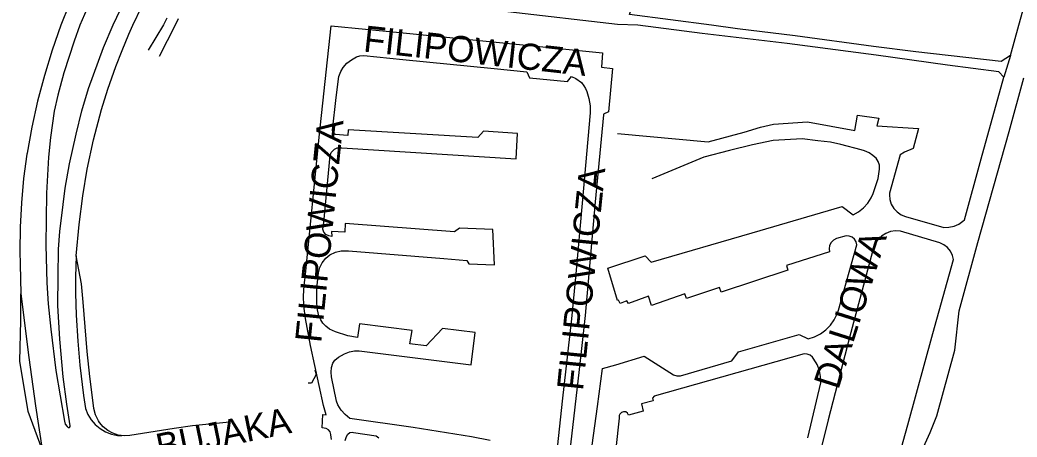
# Model space of a CAD drawing. Extents: x -304109 to -273954, y 21500 to 39796.
# Drawn here: x -293427.4 to -293046.9, y 26092.8 to 26252 of the extents above; entities that cross this region are included whole.
import ezdxf

# ---------------------------------------------------------------- set-up
doc = ezdxf.new("R2010")
doc.units = 0
doc.layers.add('krawedzie_ulic', color=7, linetype='Continuous')
doc.layers.add('nazwy_ulic', color=7, linetype='Continuous')

msp = doc.modelspace()

# ---------------------------------------------------------------- linework, layer by layer
at = {"layer": 'krawedzie_ulic'}
for points in [[(-293049.422, 26238.461), (-293046.255, 26250), (-293020.945, 26340.252), (-293018.58, 26349.347), (-293017.527, 26354.28), (-293015.976, 26362.706), (-293013.596, 26376.987), (-293012.654, 26382.031), (-293010.327, 26390.789), (-293006.508, 26405.341), (-293001.971, 26421.717), (-293001.307, 26425.819)], [(-293049.422, 26238.461), (-293052.975, 26236.155), (-293085.447, 26239.764), (-293101.608, 26241.861), (-293131.537, 26245.9), (-293153.518, 26248.648), (-293163.414, 26250), (-293194.727, 26254.097), (-293187.743, 26275.442), (-293180.973, 26295.729), (-293171.969, 26313.451), (-293167.518, 26323.093), (-293146.198, 26368.223), (-293143.014, 26376.286), (-293140.282, 26384.213)], [(-293399.999, 26260.275), (-293404.455, 26249.968), (-293406.699, 26243.829), (-293410.626, 26231.78), (-293412.907, 26223.216), (-293414.318, 26217.187), (-293415.766, 26207.122), (-293416.414, 26199.62), (-293417.252, 26185.828), (-293417.519, 26166.006), (-293417.064, 26151.722), (-293416.644, 26143.669), (-293415.577, 26134.038), (-293413.711, 26118.178), (-293410.365, 26098.884), (-293410.051, 26097.769), (-293409.379, 26096.825), (-293408.973, 26096.482), (-293408.513, 26096.517), (-293408.237, 26096.887), (-293408.229, 26097.073), (-293409.447, 26105.35), (-293410.82, 26115.769), (-293412.192, 26130.165), (-293412.877, 26143.083), (-293412.802, 26154.056), (-293412.611, 26164.474), (-293412.117, 26171.248), (-293410.82, 26181.59), (-293410.058, 26187.752), (-293408.422, 26197.084), (-293405.866, 26208.456), (-293403.736, 26217.244), (-293401.219, 26225.869), (-293395.466, 26241.42), (-293391.766, 26250.083), (-293386.347, 26261.657)], [(-293408.632, 26257.912), (-293411.755, 26250), (-293415.098, 26240.45), (-293418.061, 26230.775), (-293420.639, 26220.99), (-293422.828, 26211.111), (-293424.626, 26201.153), (-293424.697, 26200.705), (-293425.962, 26191.479), (-293426.831, 26182.208), (-293427.3, 26172.907), (-293427.369, 26163.596), (-293427.249, 26158.799), (-293427.057, 26147.446)], [(-293405.86, 26161.936), (-293404.755, 26173.897), (-293403.421, 26184.91), (-293401.707, 26195.049), (-293399.267, 26206.177), (-293396.257, 26217.76), (-293393.854, 26225.546), (-293390.77, 26234.189), (-293388.405, 26240.257), (-293385.817, 26246.572), (-293384.253, 26250.006), (-293380.862, 26257.113)], [(-293051.878, 26230.178), (-293053.847, 26232.143), (-293073.434, 26234.684), (-293100.613, 26238.48), (-293134.655, 26242.948), (-293167.001, 26246.786), (-293191.644, 26250), (-293199.376, 26250.243), (-293241.201, 26255.126)], [(-293371.322, 26252.653), (-293372.606, 26250.117), (-293378.451, 26240.425)], [(-293366.929, 26252.379), (-293368.108, 26250.021), (-293374.265, 26238.023)], [(-293308.538, 26091.929), (-293308.687, 26093.672), (-293308.697, 26093.877), (-293308.985, 26094.858), (-293309.624, 26095.657), (-293310.518, 26096.153), (-293312.082, 26096.42), (-293311.777, 26101.419), (-293310.552, 26101.287), (-293311.506, 26104.913), (-293316.456, 26127.809), (-293318.342, 26138.122), (-293319.023, 26142.893), (-293319.213, 26146.755), (-293318.91, 26150.693), (-293318.457, 26154.869), (-293313.239, 26207.239), (-293308.55, 26249.673), (-293282.434, 26247.216), (-293205.084, 26239.431), (-293205.5, 26233.979), (-293201.224, 26233.487), (-293202.813, 26216.919), (-293204.667, 26216.049), (-293204.71, 26215.836), (-293207.909, 26182.534), (-293211.718, 26139.272), (-293213.968, 26118.62), (-293217.248, 26089.909)], [(-293247.945, 26091.493), (-293255.078, 26092.943), (-293277.308, 26096.454), (-293301.526, 26099.922), (-293303.312, 26101.396), (-293304.819, 26103.154), (-293306.001, 26105.145), (-293306.561, 26106.487), (-293308.522, 26115.768), (-293308.667, 26117.649), (-293308.516, 26119.428), (-293308.024, 26121.019), (-293307.154, 26122.155), (-293305.829, 26123.29), (-293303.521, 26124.54), (-293301.553, 26125.297), (-293299.737, 26125.676), (-293297.958, 26125.676), (-293255.132, 26120.406), (-293253.626, 26132.77), (-293266.139, 26134.276), (-293272.369, 26127.627), (-293278.548, 26128.354), (-293277.702, 26133.497), (-293297.794, 26136.095), (-293298.521, 26130.796), (-293302.278, 26131.491), (-293306.932, 26133.006), (-293309.203, 26133.99), (-293310.679, 26135.088), (-293311.776, 26136.262), (-293312.608, 26137.549), (-293313.327, 26139.14), (-293313.78, 26141.441), (-293314.082, 26143.902), (-293314.043, 26149.532), (-293313.475, 26155.552), (-293312.87, 26157.585), (-293312.038, 26159.289), (-293310.676, 26161.107), (-293309.162, 26162.394), (-293307.005, 26163.417), (-293304.773, 26163.833), (-293303.07, 26163.871), (-293301.972, 26163.833), (-293265.602, 26160.987), (-293256.795, 26160.208), (-293256.017, 26158.961), (-293246.308, 26158.597), (-293246.879, 26172.052), (-293259.651, 26172.52), (-293261.52, 26171.169), (-293303.294, 26174.334), (-293303.406, 26170.969), (-293308.434, 26171.321), (-293308.401, 26169.341), (-293309.536, 26169.644), (-293310.634, 26170.174), (-293311.39, 26171.007), (-293311.769, 26172.143), (-293311.466, 26174.718), (-293308.97, 26200.284), (-293308.593, 26201.451), (-293307.382, 26202.662), (-293306.322, 26203.155), (-293304.544, 26203.155), (-293238.044, 26198.955), (-293237.477, 26208.711), (-293250.532, 26209.506), (-293252.651, 26207.083), (-293302.055, 26210.029), (-293302.206, 26207.947), (-293307.05, 26208.325), (-293307.579, 26208.59), (-293307.996, 26209.196), (-293308.109, 26209.953), (-293306.634, 26222.403), (-293305.651, 26230.449), (-293304.969, 26232.266), (-293303.986, 26233.895), (-293302.623, 26235.447), (-293300.883, 26236.772), (-293298.953, 26237.908), (-293297.704, 26238.249), (-293296.191, 26238.363), (-293281.291, 26236.887), (-293246.41, 26233.406)], [(-293049.422, 26238.461), (-293051.878, 26230.178)], [(-293246.41, 26233.406), (-293233.941, 26232.196), (-293232.957, 26229.924), (-293218.388, 26228.523), (-293216.926, 26230.453), (-293215.185, 26229.62), (-293213.104, 26228.106)], [(-293213.104, 26228.106), (-293212.158, 26226.894), (-293211.585, 26225.802), (-293211.083, 26224.649), (-293210.244, 26221.999), (-293209.793, 26219.255), (-293209.74, 26216.475)], [(-293199.349, 26208.701), (-293164.723, 26205.429), (-293150.973, 26209.133), (-293144.787, 26211.079), (-293139.793, 26212.184), (-293126.846, 26213.113), (-293108.796, 26209.753), (-293107.714, 26215.634), (-293099.583, 26214.44), (-293100.335, 26211.61), (-293084.427, 26210.549), (-293086.46, 26202.988), (-293089.862, 26201.529), (-293091.458, 26200.505), (-293095.575, 26185.883), (-293095.602, 26185.282), (-293095.421, 26183.44), (-293094.85, 26181.681), (-293093.915, 26180.084), (-293092.659, 26178.725), (-293091.141, 26177.667), (-293089.432, 26176.958), (-293074.806, 26172.846), (-293072.84, 26172.863), (-293070.918, 26173.276), (-293069.119, 26174.069), (-293067.517, 26175.209), (-293066.954, 26175.744), (-293060.541, 26198.925), (-293051.878, 26230.178)], [(-293087.193, 26075.633), (-293085.131, 26083.37), (-293080.003, 26094.565), (-293077.436, 26100.926), (-293070.552, 26126.051), (-293068.915, 26140.96), (-293061.819, 26167.015), (-293049.936, 26209.366), (-293044.316, 26229.917)], [(-293209.74, 26216.475), (-293212.789, 26182.012), (-293215.265, 26155.066), (-293216.865, 26137.964), (-293220.488, 26106.509), (-293222.241, 26089.898)], [(-293209.49, 26086.098), (-293207.035, 26104.478), (-293205.027, 26118.953), (-293199.961, 26120.442), (-293189.135, 26123.67), (-293177.921, 26116.598), (-293176.754, 26116.205), (-293175.523, 26116.204), (-293175.314, 26116.244), (-293155.766, 26121.94), (-293153.159, 26125.389), (-293130.073, 26131.922), (-293126.538, 26130.33), (-293124.142, 26131.101), (-293121.897, 26132.242), (-293119.861, 26133.723), (-293118.086, 26135.508), (-293116.614, 26137.55), (-293115.484, 26139.8), (-293114.978, 26141.242), (-293108.049, 26166.232), (-293108.277, 26167.381), (-293108.875, 26168.389), (-293109.775, 26169.138), (-293110.875, 26169.544), (-293112.046, 26169.559), (-293112.114, 26169.548), (-293115.737, 26168.575), (-293116.888, 26167.977), (-293117.804, 26167.059), (-293118.398, 26165.906), (-293118.616, 26164.628), (-293118.477, 26163.49), (-293134.85, 26158.275), (-293134.364, 26156.507), (-293159.805, 26148.109), (-293160.424, 26149.878), (-293172.987, 26145.688), (-293173.65, 26147.501), (-293186.412, 26143.083), (-293187.473, 26146.62), (-293195.192, 26143.839), (-293195.811, 26144.767), (-293198.329, 26143.794), (-293198.948, 26145.077), (-293199.309, 26144.951), (-293203.019, 26157.241), (-293188.801, 26162.025), (-293186.548, 26159.593), (-293148.015, 26170.76), (-293113.67, 26180.792), (-293109.472, 26177.564), (-293107.357, 26178.76), (-293105.466, 26180.287), (-293103.85, 26182.102), (-293102.554, 26184.158), (-293101.827, 26185.786), (-293099.849, 26191.537), (-293099.354, 26195.013), (-293099.419, 26196.51), (-293099.877, 26197.937), (-293100.694, 26199.193), (-293101.813, 26200.19), (-293101.873, 26200.23), (-293103.354, 26201.327), (-293105.036, 26202.08), (-293106.38, 26202.397), (-293114.148, 26204.425), (-293118.036, 26205.353), (-293122.941, 26205.884), (-293128.853, 26206.635), (-293139.878, 26206.016), (-293147.865, 26204.371), (-293156.614, 26202.205), (-293166.38, 26199.685), (-293186.193, 26191.343)], [(-293094.222, 26077.069), (-293088.608, 26097.482), (-293078.969, 26132.405), (-293071.148, 26160.594), (-293071.522, 26162.138), (-293072.296, 26163.732), (-293073.406, 26165.112), (-293074.796, 26166.208), (-293076.397, 26166.966), (-293091.288, 26171.387), (-293093.228, 26171.497), (-293095.15, 26171.209), (-293096.972, 26170.535), (-293098.619, 26169.502), (-293100.019, 26168.155), (-293101.116, 26166.551), (-293101.584, 26165.551), (-293110.804, 26130.76), (-293118.926, 26099.409), (-293122.765, 26084.014)], [(-293405.86, 26161.936), (-293406.187, 26153.957), (-293406.225, 26147.737), (-293405.959, 26139.285), (-293405.311, 26129.401), (-293404.475, 26120.261), (-293403.178, 26108.747), (-293402.34, 26103.728), (-293401.456, 26101.487), (-293400.215, 26099.422), (-293398.649, 26097.591), (-293396.803, 26096.043), (-293394.726, 26094.822), (-293392.476, 26093.96), (-293390.115, 26093.483), (-293388.537, 26093.384)], [(-293347.462, 26098.474), (-293361.573, 26097.062), (-293368.496, 26096.111), (-293385.414, 26093.404), (-293387.628, 26093.308), (-293389.824, 26093.61), (-293391.929, 26094.302), (-293393.877, 26095.36), (-293395.603, 26096.75), (-293397.051, 26098.427), (-293397.439, 26099.001), (-293398.473, 26101.278), (-293399.131, 26103.69), (-293399.308, 26104.878), (-293400.755, 26115.961), (-293401.746, 26125.501), (-293403.305, 26144.364), (-293403.915, 26151.251), (-293405.86, 26161.936)], [(-293418.933, 26088.053), (-293424.279, 26102.582), (-293427.347, 26121.809), (-293427.004, 26137.341), (-293427.057, 26147.446)], [(-293427.057, 26147.446), (-293424.006, 26123.228), (-293421.374, 26104.747), (-293418.933, 26088.053)], [(-293126.768, 26092.579), (-293121.734, 26113.466), (-293121.825, 26115.901), (-293122.312, 26118.288), (-293123.182, 26120.564), (-293123.501, 26121.191), (-293124.915, 26123.314), (-293124.941, 26123.346), (-293125.832, 26124.105), (-293126.926, 26124.523), (-293128.096, 26124.552), (-293185.405, 26108.422), (-293185.935, 26107.626), (-293185.759, 26106.698), (-293190.194, 26105.466)], [(-293314.787, 26118.452), (-293314.291, 26116.658), (-293316.083, 26113.338), (-293317.342, 26113.376)], [(-293190.194, 26105.466), (-293189.531, 26102.769), (-293195.098, 26101.178), (-293195.509, 26101.924), (-293196.212, 26102.404), (-293197.056, 26102.516), (-293197.86, 26102.235)], [(-293197.86, 26102.235), (-293198.451, 26101.622), (-293198.678, 26101.009), (-293198.678, 26100.028), (-293200.035, 26088.482)], [(-293303.254, 26091.579), (-293302.801, 26093.042), (-293302.253, 26093.99), (-293301.509, 26094.522), (-293300.61, 26094.69), (-293300.035, 26094.591), (-293291.377, 26093.331), (-293290.404, 26092.561)]]:
    msp.add_lwpolyline(points, dxfattribs=at)

# ---------------------------------------------------------------- texts
at = {"layer": 'nazwy_ulic'}
for s, rotation, p in [('FILIPOWICZA', 353.71073, (-293296.592, 26239.956)), ('FILIPOWICZA', 84.25433, (-293312.438, 26128.563)), ('FILIPOWICZA', 84.25433, (-293212.528, 26110.312)), ('DALIOWA', 72.42067, (-293115.084, 26110.608)), ('BUJAKA', 11.61788, (-293374.247, 26084.034))]:
    msp.add_text(s, height=10, rotation=rotation, dxfattribs=at).set_placement(p)

doc.saveas('drawing.dxf')
